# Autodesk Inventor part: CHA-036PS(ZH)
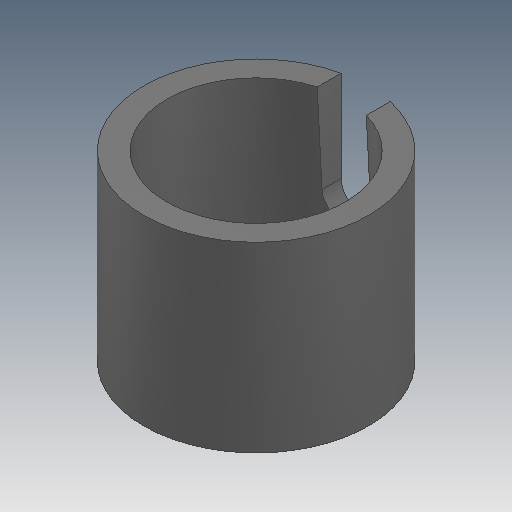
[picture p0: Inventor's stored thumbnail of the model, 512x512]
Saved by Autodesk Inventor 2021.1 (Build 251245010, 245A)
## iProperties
Created: 2021-05
Part Number: CHA-036PS(ZH)
Material: Ogólny
Document SubType Name: Modeling
Designer: user
Density: 1 g/cm^3
Appearance: Domyślna
Author: user
Revision Number: ÈÎºÎ
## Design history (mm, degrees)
feature "ÇÐ³ý-À­Éì1"
node "Bryła1"
